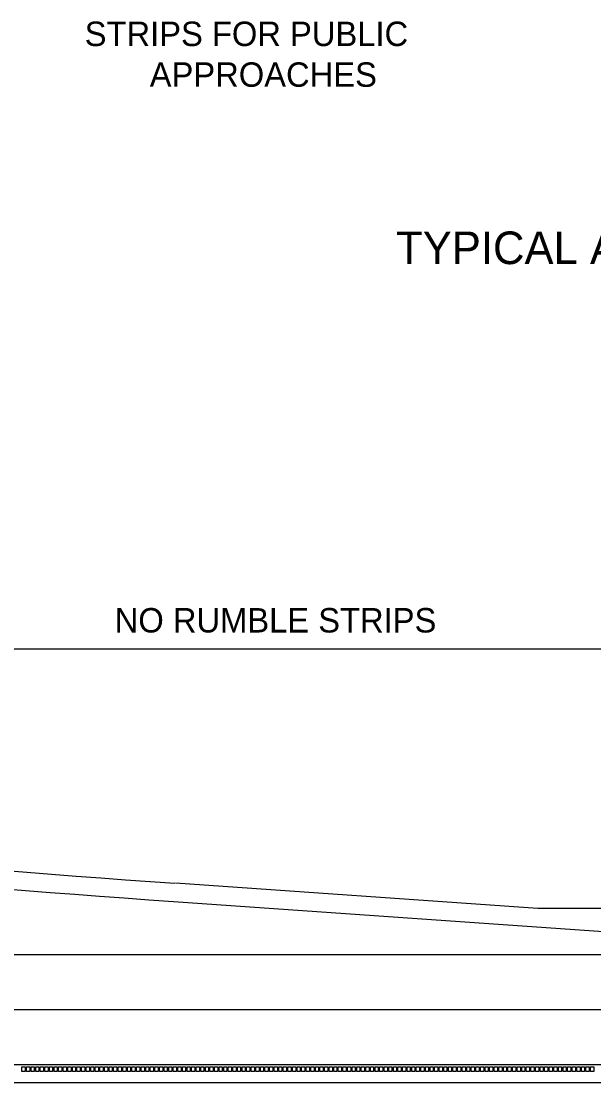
# Model space of a CAD drawing. Extents: x 49991.4 to 50021, y 49987.6 to 50011.4.
# Drawn here: x 50006.626 to 50008.031, y 49990.455 to 49993.06 of the extents above; entities that cross this region are included whole.
import ezdxf

# ---------------------------------------------------------------- set-up
doc = ezdxf.new("R2010")
doc.units = 0
for name, color, linetype in [('Level 1', 7, 'Continuous'), ('Level 2', 7, 'Continuous'), ('Level 3', 7, 'Continuous')]:
    doc.layers.add(name, color=color, linetype=linetype)

msp = doc.modelspace()

# ---------------------------------------------------------------- linework, layer by layer
at = {"layer": 'Level 1'}
for p, q in [((50007.8935, 49990.8823), (50007.0052, 49990.9444)), ((50007.0002, 49990.8996), (50008.8555, 49990.7698)), ((50012.4393, 49990.8823), (50007.8935, 49990.8823)), ((50005.9012, 49990.7698), (50012.4393, 49990.7698)), ((50005.9012, 49990.6348), (50012.4393, 49990.6348)), ((50005.9012, 49990.4998), (50012.4393, 49990.4998)), ((50012.4393, 49990.4548), (50005.9012, 49990.4548))]:
    msp.add_line(p, q, dxfattribs=at)
for points in [[(50006.6359, 49990.4828), (50006.6281, 49990.4828), (50006.6281, 49990.494), (50006.6359, 49990.494)], [(50006.6472, 49990.4828), (50006.6393, 49990.4828), (50006.6393, 49990.494), (50006.6472, 49990.494)], [(50006.6585, 49990.4828), (50006.6505, 49990.4828), (50006.6505, 49990.494), (50006.6585, 49990.494)], [(50006.6697, 49990.4828), (50006.6619, 49990.4828), (50006.6619, 49990.494), (50006.6697, 49990.494)], [(50006.6809, 49990.4828), (50006.6731, 49990.4828), (50006.6731, 49990.494), (50006.6809, 49990.494)], [(50006.6922, 49990.4828), (50006.6843, 49990.4828), (50006.6843, 49990.494), (50006.6922, 49990.494)], [(50006.7035, 49990.4828), (50006.6955, 49990.4828), (50006.6955, 49990.494), (50006.7035, 49990.494)], [(50006.7147, 49990.4828), (50006.7069, 49990.4828), (50006.7069, 49990.494), (50006.7147, 49990.494)], [(50006.7259, 49990.4828), (50006.7181, 49990.4828), (50006.7181, 49990.494), (50006.7259, 49990.494)], [(50006.7372, 49990.4828), (50006.7293, 49990.4828), (50006.7293, 49990.494), (50006.7372, 49990.494)], [(50006.7485, 49990.4828), (50006.7405, 49990.4828), (50006.7405, 49990.494), (50006.7485, 49990.494)], [(50006.7597, 49990.4828), (50006.7519, 49990.4828), (50006.7519, 49990.494), (50006.7597, 49990.494)], [(50006.7709, 49990.4828), (50006.7631, 49990.4828), (50006.7631, 49990.494), (50006.7709, 49990.494)], [(50006.7822, 49990.4828), (50006.7743, 49990.4828), (50006.7743, 49990.494), (50006.7822, 49990.494)], [(50006.7935, 49990.4828), (50006.7855, 49990.4828), (50006.7855, 49990.494), (50006.7935, 49990.494)], [(50006.8047, 49990.4828), (50006.7969, 49990.4828), (50006.7969, 49990.494), (50006.8047, 49990.494)], [(50006.8159, 49990.4828), (50006.8081, 49990.4828), (50006.8081, 49990.494), (50006.8159, 49990.494)], [(50006.8272, 49990.4828), (50006.8193, 49990.4828), (50006.8193, 49990.494), (50006.8272, 49990.494)], [(50006.8385, 49990.4828), (50006.8305, 49990.4828), (50006.8305, 49990.494), (50006.8385, 49990.494)], [(50006.8497, 49990.4828), (50006.8419, 49990.4828), (50006.8419, 49990.494), (50006.8497, 49990.494)], [(50006.8609, 49990.4828), (50006.8531, 49990.4828), (50006.8531, 49990.494), (50006.8609, 49990.494)], [(50006.8722, 49990.4828), (50006.8643, 49990.4828), (50006.8643, 49990.494), (50006.8722, 49990.494)], [(50006.8835, 49990.4828), (50006.8755, 49990.4828), (50006.8755, 49990.494), (50006.8835, 49990.494)], [(50006.8947, 49990.4828), (50006.8869, 49990.4828), (50006.8869, 49990.494), (50006.8947, 49990.494)], [(50006.9059, 49990.4828), (50006.8981, 49990.4828), (50006.8981, 49990.494), (50006.9059, 49990.494)], [(50006.9172, 49990.4828), (50006.9093, 49990.4828), (50006.9093, 49990.494), (50006.9172, 49990.494)], [(50006.9285, 49990.4828), (50006.9205, 49990.4828), (50006.9205, 49990.494), (50006.9285, 49990.494)], [(50006.9397, 49990.4828), (50006.9319, 49990.4828), (50006.9319, 49990.494), (50006.9397, 49990.494)], [(50006.9509, 49990.4828), (50006.9431, 49990.4828), (50006.9431, 49990.494), (50006.9509, 49990.494)], [(50006.9622, 49990.4828), (50006.9543, 49990.4828), (50006.9543, 49990.494), (50006.9622, 49990.494)], [(50006.9735, 49990.4828), (50006.9655, 49990.4828), (50006.9655, 49990.494), (50006.9735, 49990.494)], [(50006.9847, 49990.4828), (50006.9769, 49990.4828), (50006.9769, 49990.494), (50006.9847, 49990.494)], [(50006.9959, 49990.4828), (50006.9881, 49990.4828), (50006.9881, 49990.494), (50006.9959, 49990.494)], [(50007.0072, 49990.4828), (50006.9993, 49990.4828), (50006.9993, 49990.494), (50007.0072, 49990.494)], [(50007.0185, 49990.4828), (50007.0105, 49990.4828), (50007.0105, 49990.494), (50007.0185, 49990.494)], [(50007.0297, 49990.4828), (50007.0219, 49990.4828), (50007.0219, 49990.494), (50007.0297, 49990.494)], [(50007.0409, 49990.4828), (50007.0331, 49990.4828), (50007.0331, 49990.494), (50007.0409, 49990.494)], [(50007.0522, 49990.4828), (50007.0443, 49990.4828), (50007.0443, 49990.494), (50007.0522, 49990.494)], [(50007.0635, 49990.4828), (50007.0555, 49990.4828), (50007.0555, 49990.494), (50007.0635, 49990.494)], [(50007.0747, 49990.4828), (50007.0669, 49990.4828), (50007.0669, 49990.494), (50007.0747, 49990.494)], [(50007.0859, 49990.4828), (50007.0781, 49990.4828), (50007.0781, 49990.494), (50007.0859, 49990.494)], [(50007.0972, 49990.4828), (50007.0893, 49990.4828), (50007.0893, 49990.494), (50007.0972, 49990.494)], [(50007.1085, 49990.4828), (50007.1005, 49990.4828), (50007.1005, 49990.494), (50007.1085, 49990.494)], [(50007.1197, 49990.4828), (50007.1119, 49990.4828), (50007.1119, 49990.494), (50007.1197, 49990.494)], [(50007.1309, 49990.4828), (50007.1231, 49990.4828), (50007.1231, 49990.494), (50007.1309, 49990.494)], [(50007.1422, 49990.4828), (50007.1343, 49990.4828), (50007.1343, 49990.494), (50007.1422, 49990.494)], [(50007.1535, 49990.4828), (50007.1455, 49990.4828), (50007.1455, 49990.494), (50007.1535, 49990.494)], [(50007.1647, 49990.4828), (50007.1569, 49990.4828), (50007.1569, 49990.494), (50007.1647, 49990.494)], [(50007.1759, 49990.4828), (50007.1681, 49990.4828), (50007.1681, 49990.494), (50007.1759, 49990.494)], [(50007.1872, 49990.4828), (50007.1793, 49990.4828), (50007.1793, 49990.494), (50007.1872, 49990.494)], [(50007.1985, 49990.4828), (50007.1905, 49990.4828), (50007.1905, 49990.494), (50007.1985, 49990.494)], [(50007.2097, 49990.4828), (50007.2019, 49990.4828), (50007.2019, 49990.494), (50007.2097, 49990.494)], [(50007.2209, 49990.4828), (50007.2131, 49990.4828), (50007.2131, 49990.494), (50007.2209, 49990.494)], [(50007.2322, 49990.4828), (50007.2243, 49990.4828), (50007.2243, 49990.494), (50007.2322, 49990.494)], [(50007.2435, 49990.4828), (50007.2355, 49990.4828), (50007.2355, 49990.494), (50007.2435, 49990.494)], [(50007.2547, 49990.4828), (50007.2469, 49990.4828), (50007.2469, 49990.494), (50007.2547, 49990.494)], [(50007.2659, 49990.4828), (50007.2581, 49990.4828), (50007.2581, 49990.494), (50007.2659, 49990.494)], [(50007.2772, 49990.4828), (50007.2693, 49990.4828), (50007.2693, 49990.494), (50007.2772, 49990.494)], [(50007.2885, 49990.4828), (50007.2805, 49990.4828), (50007.2805, 49990.494), (50007.2885, 49990.494)], [(50007.2997, 49990.4828), (50007.2919, 49990.4828), (50007.2919, 49990.494), (50007.2997, 49990.494)], [(50007.3109, 49990.4828), (50007.3031, 49990.4828), (50007.3031, 49990.494), (50007.3109, 49990.494)], [(50007.3222, 49990.4828), (50007.3143, 49990.4828), (50007.3143, 49990.494), (50007.3222, 49990.494)], [(50007.3335, 49990.4828), (50007.3255, 49990.4828), (50007.3255, 49990.494), (50007.3335, 49990.494)], [(50007.3447, 49990.4828), (50007.3369, 49990.4828), (50007.3369, 49990.494), (50007.3447, 49990.494)], [(50007.3559, 49990.4828), (50007.3481, 49990.4828), (50007.3481, 49990.494), (50007.3559, 49990.494)], [(50007.3672, 49990.4828), (50007.3593, 49990.4828), (50007.3593, 49990.494), (50007.3672, 49990.494)], [(50007.3785, 49990.4828), (50007.3705, 49990.4828), (50007.3705, 49990.494), (50007.3785, 49990.494)], [(50007.3897, 49990.4828), (50007.3819, 49990.4828), (50007.3819, 49990.494), (50007.3897, 49990.494)], [(50007.4009, 49990.4828), (50007.3931, 49990.4828), (50007.3931, 49990.494), (50007.4009, 49990.494)], [(50007.4122, 49990.4828), (50007.4043, 49990.4828), (50007.4043, 49990.494), (50007.4122, 49990.494)], [(50007.4235, 49990.4828), (50007.4155, 49990.4828), (50007.4155, 49990.494), (50007.4235, 49990.494)], [(50007.4347, 49990.4828), (50007.4269, 49990.4828), (50007.4269, 49990.494), (50007.4347, 49990.494)], [(50007.4459, 49990.4828), (50007.4381, 49990.4828), (50007.4381, 49990.494), (50007.4459, 49990.494)], [(50007.4572, 49990.4828), (50007.4493, 49990.4828), (50007.4493, 49990.494), (50007.4572, 49990.494)], [(50007.4685, 49990.4828), (50007.4605, 49990.4828), (50007.4605, 49990.494), (50007.4685, 49990.494)], [(50007.4797, 49990.4828), (50007.4719, 49990.4828), (50007.4719, 49990.494), (50007.4797, 49990.494)], [(50007.4909, 49990.4828), (50007.4831, 49990.4828), (50007.4831, 49990.494), (50007.4909, 49990.494)], [(50007.5022, 49990.4828), (50007.4943, 49990.4828), (50007.4943, 49990.494), (50007.5022, 49990.494)], [(50007.5135, 49990.4828), (50007.5055, 49990.4828), (50007.5055, 49990.494), (50007.5135, 49990.494)], [(50007.5247, 49990.4828), (50007.5169, 49990.4828), (50007.5169, 49990.494), (50007.5247, 49990.494)], [(50007.5359, 49990.4828), (50007.5281, 49990.4828), (50007.5281, 49990.494), (50007.5359, 49990.494)], [(50007.5472, 49990.4828), (50007.5393, 49990.4828), (50007.5393, 49990.494), (50007.5472, 49990.494)], [(50007.5585, 49990.4828), (50007.5505, 49990.4828), (50007.5505, 49990.494), (50007.5585, 49990.494)], [(50007.5697, 49990.4828), (50007.5619, 49990.4828), (50007.5619, 49990.494), (50007.5697, 49990.494)], [(50007.5809, 49990.4828), (50007.5731, 49990.4828), (50007.5731, 49990.494), (50007.5809, 49990.494)], [(50007.5922, 49990.4828), (50007.5843, 49990.4828), (50007.5843, 49990.494), (50007.5922, 49990.494)], [(50007.6035, 49990.4828), (50007.5955, 49990.4828), (50007.5955, 49990.494), (50007.6035, 49990.494)], [(50007.6147, 49990.4828), (50007.6069, 49990.4828), (50007.6069, 49990.494), (50007.6147, 49990.494)], [(50007.6259, 49990.4828), (50007.6181, 49990.4828), (50007.6181, 49990.494), (50007.6259, 49990.494)], [(50007.6372, 49990.4828), (50007.6293, 49990.4828), (50007.6293, 49990.494), (50007.6372, 49990.494)], [(50007.6485, 49990.4828), (50007.6405, 49990.4828), (50007.6405, 49990.494), (50007.6485, 49990.494)], [(50007.6597, 49990.4828), (50007.6519, 49990.4828), (50007.6519, 49990.494), (50007.6597, 49990.494)], [(50007.6709, 49990.4828), (50007.6631, 49990.4828), (50007.6631, 49990.494), (50007.6709, 49990.494)], [(50007.6822, 49990.4828), (50007.6743, 49990.4828), (50007.6743, 49990.494), (50007.6822, 49990.494)], [(50007.6935, 49990.4828), (50007.6855, 49990.4828), (50007.6855, 49990.494), (50007.6935, 49990.494)], [(50007.7047, 49990.4828), (50007.6969, 49990.4828), (50007.6969, 49990.494), (50007.7047, 49990.494)], [(50007.7159, 49990.4828), (50007.7081, 49990.4828), (50007.7081, 49990.494), (50007.7159, 49990.494)], [(50007.7272, 49990.4828), (50007.7193, 49990.4828), (50007.7193, 49990.494), (50007.7272, 49990.494)], [(50007.7385, 49990.4828), (50007.7305, 49990.4828), (50007.7305, 49990.494), (50007.7385, 49990.494)], [(50007.7497, 49990.4828), (50007.7419, 49990.4828), (50007.7419, 49990.494), (50007.7497, 49990.494)], [(50007.7609, 49990.4828), (50007.7531, 49990.4828), (50007.7531, 49990.494), (50007.7609, 49990.494)], [(50007.7722, 49990.4828), (50007.7643, 49990.4828), (50007.7643, 49990.494), (50007.7722, 49990.494)], [(50007.7835, 49990.4828), (50007.7755, 49990.4828), (50007.7755, 49990.494), (50007.7835, 49990.494)], [(50007.7947, 49990.4828), (50007.7869, 49990.4828), (50007.7869, 49990.494), (50007.7947, 49990.494)], [(50007.8059, 49990.4828), (50007.7981, 49990.4828), (50007.7981, 49990.494), (50007.8059, 49990.494)], [(50007.8172, 49990.4828), (50007.8093, 49990.4828), (50007.8093, 49990.494), (50007.8172, 49990.494)], [(50007.8285, 49990.4828), (50007.8205, 49990.4828), (50007.8205, 49990.494), (50007.8285, 49990.494)], [(50007.8397, 49990.4828), (50007.8319, 49990.4828), (50007.8319, 49990.494), (50007.8397, 49990.494)], [(50007.8509, 49990.4828), (50007.8431, 49990.4828), (50007.8431, 49990.494), (50007.8509, 49990.494)], [(50007.8622, 49990.4828), (50007.8543, 49990.4828), (50007.8543, 49990.494), (50007.8622, 49990.494)], [(50007.8735, 49990.4828), (50007.8655, 49990.4828), (50007.8655, 49990.494), (50007.8735, 49990.494)], [(50007.8847, 49990.4828), (50007.8769, 49990.4828), (50007.8769, 49990.494), (50007.8847, 49990.494)], [(50007.8959, 49990.4828), (50007.8881, 49990.4828), (50007.8881, 49990.494), (50007.8959, 49990.494)], [(50007.9072, 49990.4828), (50007.8993, 49990.4828), (50007.8993, 49990.494), (50007.9072, 49990.494)], [(50007.9185, 49990.4828), (50007.9105, 49990.4828), (50007.9105, 49990.494), (50007.9185, 49990.494)], [(50007.9297, 49990.4828), (50007.9219, 49990.4828), (50007.9219, 49990.494), (50007.9297, 49990.494)], [(50007.9409, 49990.4828), (50007.9331, 49990.4828), (50007.9331, 49990.494), (50007.9409, 49990.494)], [(50007.9522, 49990.4828), (50007.9443, 49990.4828), (50007.9443, 49990.494), (50007.9522, 49990.494)], [(50007.9635, 49990.4828), (50007.9555, 49990.4828), (50007.9555, 49990.494), (50007.9635, 49990.494)], [(50007.9747, 49990.4828), (50007.9669, 49990.4828), (50007.9669, 49990.494), (50007.9747, 49990.494)], [(50007.9859, 49990.4828), (50007.9781, 49990.4828), (50007.9781, 49990.494), (50007.9859, 49990.494)], [(50007.9972, 49990.4828), (50007.9893, 49990.4828), (50007.9893, 49990.494), (50007.9972, 49990.494)], [(50008.0085, 49990.4828), (50008.0005, 49990.4828), (50008.0005, 49990.494), (50008.0085, 49990.494)], [(50008.0197, 49990.4828), (50008.0119, 49990.4828), (50008.0119, 49990.494), (50008.0197, 49990.494)], [(50008.0309, 49990.4828), (50008.0231, 49990.4828), (50008.0231, 49990.494), (50008.0309, 49990.494)]]:
    msp.add_lwpolyline(points, close=True, dxfattribs=at)
for radius in [43.6176, 43.6626]:
    msp.add_arc((50010.046, 50034.4559), radius, 260.9, 266, dxfattribs=at)
at = {"layer": 'Level 3'}
msp.add_line((50004.638, 49991.5198), (50009.9805, 49991.5198), dxfattribs=at)

# ---------------------------------------------------------------- texts
at = {"layer": 'Level 2'}
for s, height, p in [('STRIPS FOR PUBLIC', 0.06, (50006.7821, 49992.999)), ('APPROACHES', 0.06, (50006.9416, 49992.899)), ('TYPICAL APPLICATION', 0.08, (50007.546, 49992.4639)), ('NO RUMBLE STRIPS', 0.06, (50006.8557, 49991.5598))]:
    msp.add_text(s, height=height, dxfattribs=at).set_placement(p)

doc.saveas('drawing.dxf')
